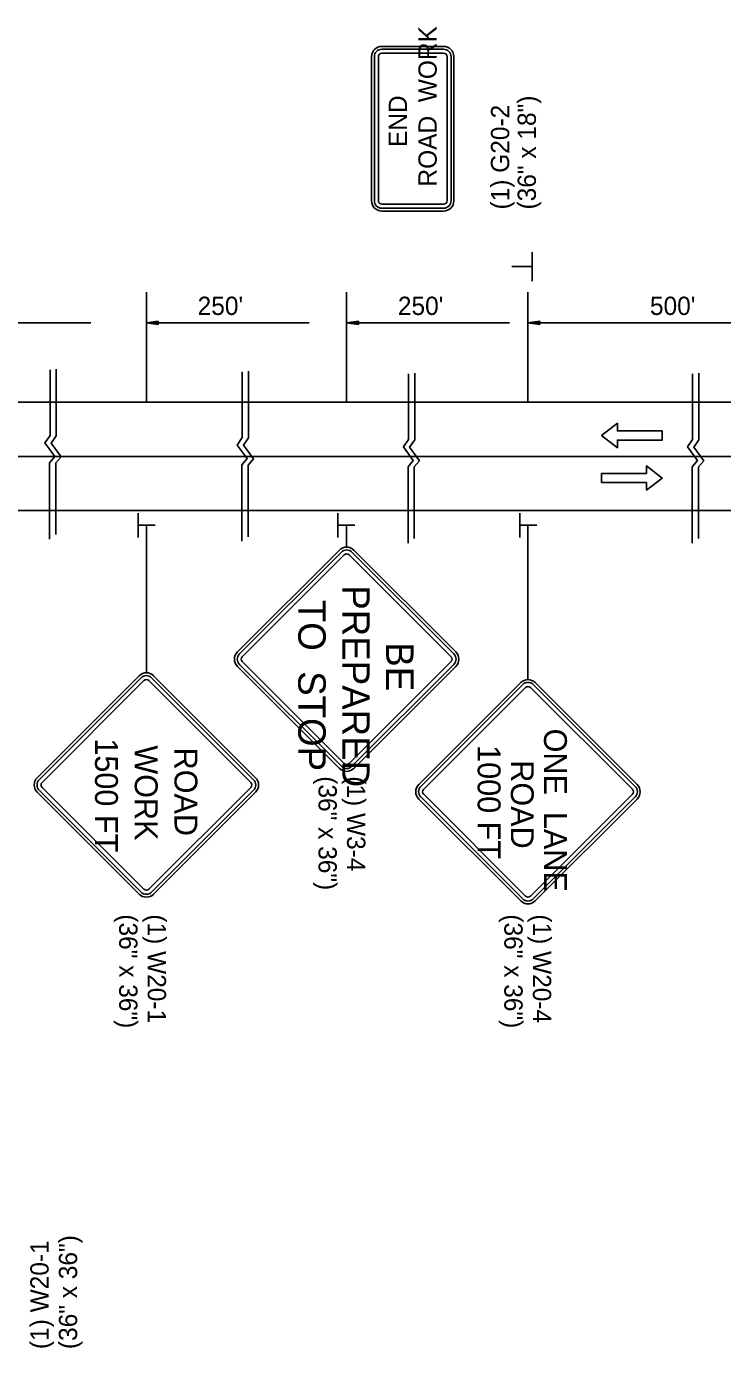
# Model space of a CAD drawing. Extents: x 1927831 to 1930787, y 596452 to 597699.
# Drawn here: x 1928240.2 to 1928468.4, y 597195.5 to 597628.8 of the extents above; entities that cross this region are included whole.
import ezdxf

# ---------------------------------------------------------------- set-up
doc = ezdxf.new("R2010")
doc.units = 0
for name, color, linetype in [('Default', 7, 'Continuous'), ('P_TC_Signs_Permanent', 7, 'Continuous'), ('P_TC_Signs_Temporary', 7, 'Continuous'), ('R_Annotation', 7, 'Continuous'), ('R_Striping', 7, 'Continuous')]:
    doc.layers.add(name, color=color, linetype=linetype)

msp = doc.modelspace()

# ---------------------------------------------------------------- linework, layer by layer
at = {"layer": 'Default'}
for p, q in [((1928406.01, 597554.74), (1928406.01, 597545.26)), ((1928405.87, 597550.02), (1928399.4, 597550.02)), ((1928279.55, 597541.61), (1928279.55, 597505.58)), ((1928345.2, 597541.61), (1928345.2, 597505.58)), ((1928404.65, 597541.61), (1928404.65, 597505.58)), ((1928207.95, 597531.57), (1928261.36, 597531.59)), ((1928283.39, 597532.16), (1928279.55, 597531.59)), ((1928279.55, 597531.59), (1928332.95, 597531.59)), ((1928283.39, 597531.01), (1928279.55, 597531.59)), ((1928283.39, 597532.07), (1928280.19, 597531.59)), ((1928283.39, 597531.11), (1928280.19, 597531.59)), ((1928283.39, 597531.97), (1928280.85, 597531.59)), ((1928283.39, 597531.2), (1928280.85, 597531.59)), ((1928283.39, 597531.87), (1928281.49, 597531.59)), ((1928283.39, 597531.3), (1928281.49, 597531.59)), ((1928283.39, 597531.77), (1928282.14, 597531.59)), ((1928283.39, 597531.4), (1928282.14, 597531.59)), ((1928283.39, 597531.68), (1928282.78, 597531.59)), ((1928283.39, 597531.5), (1928282.78, 597531.59)), ((1928283.39, 597531.01), (1928283.39, 597532.16)), ((1928349.04, 597532.14), (1928345.2, 597531.57)), ((1928345.2, 597531.57), (1928398.6, 597531.57)), ((1928349.04, 597530.99), (1928345.2, 597531.57)), ((1928349.04, 597532.05), (1928345.84, 597531.57)), ((1928349.04, 597531.09), (1928345.84, 597531.57)), ((1928349.04, 597531.95), (1928346.5, 597531.57)), ((1928349.04, 597531.18), (1928346.5, 597531.57)), ((1928349.04, 597531.85), (1928347.14, 597531.57)), ((1928349.04, 597531.28), (1928347.14, 597531.57)), ((1928349.04, 597531.75), (1928347.79, 597531.57)), ((1928349.04, 597531.38), (1928347.79, 597531.57)), ((1928349.04, 597531.66), (1928348.43, 597531.57)), ((1928349.04, 597531.48), (1928348.43, 597531.57)), ((1928349.04, 597530.99), (1928349.04, 597532.14)), ((1928408.49, 597532.14), (1928404.65, 597531.57)), ((1928404.65, 597531.57), (1928504.41, 597531.57)), ((1928408.49, 597530.99), (1928404.65, 597531.57)), ((1928408.49, 597532.05), (1928405.3, 597531.57)), ((1928408.49, 597531.09), (1928405.3, 597531.57)), ((1928408.49, 597531.95), (1928405.96, 597531.57)), ((1928408.49, 597531.18), (1928405.96, 597531.57)), ((1928408.49, 597531.85), (1928406.59, 597531.57)), ((1928408.49, 597531.28), (1928406.59, 597531.57)), ((1928408.49, 597531.75), (1928407.24, 597531.57)), ((1928408.49, 597531.38), (1928407.24, 597531.57)), ((1928408.49, 597531.66), (1928407.89, 597531.57)), ((1928408.49, 597531.48), (1928407.89, 597531.57)), ((1928408.49, 597530.99), (1928408.49, 597532.14)), ((1928044.85, 597505.58), (1929173.7, 597505.58)), ((1927908.3, 597487.79), (1929173.7, 597487.79)), ((1928044.85, 597470), (1929173.7, 597470)), ((1928276.87, 597461.2), (1928276.87, 597469.2)), ((1928342.35, 597461.2), (1928342.35, 597469.2)), ((1928401.98, 597461.2), (1928401.98, 597469.2)), ((1928276.99, 597465.18), (1928282.45, 597465.18)), ((1928342.47, 597465.18), (1928347.93, 597465.18)), ((1928402.1, 597465.18), (1928407.56, 597465.18))]:
    msp.add_line(p, q, dxfattribs=at)
for points in [[(1928247.96, 597516.18), (1928247.96, 597494.66), (1928246.3, 597492.19), (1928249.53, 597487.76), (1928247.83, 597485.71), (1928247.82, 597460.68)], [(1928250, 597516.37), (1928250, 597494.57), (1928248.34, 597492.1), (1928251.58, 597487.67), (1928249.87, 597485.62), (1928249.87, 597462.12)], [(1928311, 597515.51), (1928311, 597493.99), (1928309.34, 597491.51), (1928312.58, 597487.08), (1928310.87, 597485.04), (1928310.87, 597460.01)], [(1928313.04, 597515.7), (1928313.04, 597493.9), (1928311.38, 597491.43), (1928314.62, 597487), (1928312.91, 597484.95), (1928312.91, 597461.45)], [(1928365.46, 597514.86), (1928365.46, 597493.34), (1928363.8, 597490.87), (1928367.04, 597486.44), (1928365.33, 597484.39), (1928365.33, 597459.37)], [(1928367.5, 597515.06), (1928367.5, 597493.25), (1928365.84, 597490.78), (1928369.08, 597486.35), (1928367.38, 597484.31), (1928367.37, 597460.81)], [(1928458.63, 597514.86), (1928458.63, 597493.34), (1928456.96, 597490.87), (1928460.2, 597486.44), (1928458.5, 597484.39), (1928458.49, 597459.37)], [(1928460.67, 597515.06), (1928460.67, 597493.25), (1928459.01, 597490.78), (1928462.25, 597486.35), (1928460.54, 597484.31), (1928460.54, 597460.81)]]:
    msp.add_lwpolyline(points, dxfattribs=at)
at = {"layer": 'P_TC_Signs_Permanent'}
for p, q in [((1928342.81, 597457.08), (1928309.4, 597423.67)), ((1928343.48, 597456.42), (1928310.07, 597423.01)), ((1928344.41, 597455.49), (1928310.99, 597422.08)), ((1928379.41, 597422.08), (1928346, 597455.49)), ((1928380.34, 597423.01), (1928346.92, 597456.42)), ((1928381, 597423.67), (1928347.59, 597457.08)), ((1928309.4, 597418.89), (1928342.81, 597385.48)), ((1928310.07, 597419.56), (1928343.48, 597386.15)), ((1928310.99, 597420.49), (1928344.41, 597387.08)), ((1928346, 597387.08), (1928379.41, 597420.49)), ((1928346.92, 597386.15), (1928380.34, 597419.56)), ((1928347.59, 597385.48), (1928381, 597418.89))]:
    msp.add_line(p, q, dxfattribs=at)
for centre, radius, start, end in [((1928345.2, 597454.69), 3.37, 45, 135), ((1928345.2, 597454.69), 2.44, 45, 135), ((1928345.2, 597454.69), 1.13, 45, 135), ((1928311.79, 597421.28), 3.37, 135, 225), ((1928378.61, 597421.28), 3.37, 315, 45), ((1928311.79, 597421.28), 2.44, 135, 225), ((1928311.79, 597421.28), 1.13, 135, 225), ((1928378.61, 597421.28), 1.13, 315, 45), ((1928378.61, 597421.28), 2.44, 315, 45), ((1928345.2, 597387.87), 3.37, 225, 315), ((1928345.2, 597387.87), 2.44, 225, 315), ((1928345.2, 597387.87), 1.13, 225, 315)]:
    msp.add_arc(centre, radius, start, end, dxfattribs=at)
at = {"layer": 'P_TC_Signs_Temporary'}
for p, q in [((1928353.35, 597618.86), (1928353.35, 597571.61)), ((1928354.29, 597618.86), (1928354.29, 597571.61)), ((1928355.6, 597618.86), (1928355.6, 597571.61)), ((1928376.98, 597622.24), (1928356.73, 597622.24)), ((1928376.98, 597621.3), (1928356.73, 597621.3)), ((1928376.98, 597619.99), (1928356.73, 597619.99)), ((1928378.1, 597571.61), (1928378.1, 597618.86)), ((1928379.41, 597571.61), (1928379.41, 597618.86)), ((1928380.35, 597571.61), (1928380.35, 597618.86)), ((1928356.73, 597570.49), (1928376.98, 597570.49)), ((1928356.73, 597569.17), (1928376.98, 597569.17)), ((1928356.73, 597568.24), (1928376.98, 597568.24)), ((1928243.75, 597382.42), (1928277.16, 597415.83)), ((1928244.41, 597381.76), (1928277.82, 597415.17)), ((1928281.27, 597415.17), (1928314.68, 597381.76)), ((1928281.93, 597415.83), (1928315.35, 597382.42)), ((1928245.34, 597380.83), (1928278.75, 597414.24)), ((1928280.34, 597414.24), (1928313.75, 597380.83)), ((1928368.86, 597380.2), (1928402.27, 597413.61)), ((1928369.52, 597379.54), (1928402.93, 597412.95)), ((1928370.45, 597378.61), (1928403.86, 597412.02)), ((1928405.45, 597412.02), (1928438.86, 597378.61)), ((1928406.38, 597412.95), (1928439.79, 597379.54)), ((1928407.04, 597413.61), (1928440.45, 597380.2)), ((1928277.16, 597344.24), (1928243.75, 597377.65)), ((1928277.82, 597344.9), (1928244.41, 597378.31)), ((1928278.75, 597345.83), (1928245.34, 597379.24)), ((1928313.75, 597379.24), (1928280.34, 597345.83)), ((1928314.68, 597378.31), (1928281.27, 597344.9)), ((1928315.35, 597377.65), (1928281.93, 597344.24)), ((1928402.27, 597342.02), (1928368.86, 597375.43)), ((1928402.93, 597342.68), (1928369.52, 597376.09)), ((1928403.86, 597343.61), (1928370.45, 597377.02)), ((1928438.86, 597377.02), (1928405.45, 597343.61)), ((1928439.79, 597376.09), (1928406.38, 597342.68)), ((1928440.45, 597375.43), (1928407.04, 597342.02))]:
    msp.add_line(p, q, dxfattribs=at)
for centre, radius, start, end in [((1928356.73, 597618.86), 3.37, 90, 180), ((1928356.73, 597618.86), 2.44, 90, 180), ((1928356.73, 597618.86), 1.13, 90, 180), ((1928376.98, 597618.86), 3.37, 360, 90), ((1928376.98, 597618.86), 2.44, 360, 90), ((1928376.98, 597618.86), 1.13, 360, 90), ((1928356.73, 597571.61), 3.37, 180, 270), ((1928356.73, 597571.61), 2.44, 180, 270), ((1928356.73, 597571.61), 1.13, 180, 270), ((1928376.98, 597571.61), 2.44, 270, 360), ((1928376.98, 597571.61), 1.13, 270, 360), ((1928376.98, 597571.61), 3.37, 270, 360), ((1928279.55, 597413.45), 3.37, 45, 135), ((1928279.55, 597413.45), 2.44, 45, 135), ((1928279.55, 597413.45), 1.12, 45, 135), ((1928404.65, 597411.22), 3.37, 45, 135), ((1928404.65, 597411.22), 2.44, 45, 135), ((1928404.65, 597411.22), 1.12, 45, 135), ((1928246.14, 597380.04), 3.37, 135, 225), ((1928246.14, 597380.04), 2.44, 135, 225), ((1928246.14, 597380.04), 1.13, 135, 225), ((1928312.96, 597380.04), 1.13, 315, 45), ((1928312.96, 597380.04), 2.44, 315, 45), ((1928312.96, 597380.04), 3.37, 315, 45), ((1928371.24, 597377.81), 3.37, 135, 225), ((1928438.06, 597377.81), 3.37, 315, 45), ((1928371.24, 597377.81), 2.44, 135, 225), ((1928371.24, 597377.81), 1.13, 135, 225), ((1928438.06, 597377.81), 1.13, 315, 45), ((1928438.06, 597377.81), 2.44, 315, 45), ((1928279.55, 597346.63), 1.12, 225, 315), ((1928279.55, 597346.63), 3.37, 225, 315), ((1928279.55, 597346.63), 2.44, 225, 315), ((1928404.65, 597344.4), 3.37, 225, 315), ((1928404.65, 597344.4), 2.44, 225, 315), ((1928404.65, 597344.4), 1.12, 225, 315)]:
    msp.add_arc(centre, radius, start, end, dxfattribs=at)
at = {"layer": 'R_Annotation'}
for p, q in [((1928279.55, 597465.18), (1928279.55, 597416.82)), ((1928345.2, 597465.18), (1928345.2, 597458.07)), ((1928404.65, 597465.18), (1928404.65, 597414.6))]:
    msp.add_line(p, q, dxfattribs=at)
at = {"layer": 'R_Striping'}
for points in [[(1928433.95, 597498.63), (1928428.75, 597494.63), (1928433.95, 597490.63), (1928433.95, 597493.13), (1928448.66, 597493.13), (1928448.66, 597496.13), (1928433.95, 597496.13)], [(1928443.47, 597476.68), (1928448.66, 597480.68), (1928443.47, 597484.68), (1928443.47, 597482.18), (1928428.75, 597482.18), (1928428.75, 597479.18), (1928443.47, 597479.18)]]:
    msp.add_lwpolyline(points, close=True, dxfattribs=at)

# ---------------------------------------------------------------- texts
at = {"layer": 'Default'}
for s, p in [("250'", (1928296.35, 597534.16)), ("250'", (1928362, 597534.16)), ("500'", (1928444.63, 597534.16))]:
    msp.add_text(s, height=6, rotation=360, dxfattribs=at).set_placement(p)
at = {"layer": 'P_TC_Signs_Temporary'}
for s, height, rotation, p in [('ROAD  WORK', 6, 90, (1928374.73, 597576.28)), ('END', 6, 90, (1928364.98, 597589.21)), ('TO  STOP', 9, 270, (1928329.33, 597440.75)), ('PREPARED', 9, 270, (1928343.73, 597445.52)), ('BE', 9, 270, (1928358.13, 597426.83)), ('ONE  LANE', 7.5, 270, (1928409.9, 597398.51)), ('1500 FT', 7.5, 270, (1928262.71, 597395.33)), ('WORK', 7.5, 270, (1928275.74, 597393.03)), (' ROAD ', 7.5, 270, (1928288.76, 597395.06)), ('1000 FT', 7.5, 270, (1928388.15, 597393.1)), ('ROAD', 7.5, 270, (1928399.03, 597388.12))]:
    msp.add_text(s, height=height, rotation=rotation, dxfattribs=at).set_placement(p)
at = {"layer": 'R_Annotation'}
for s, height, rotation, p in [('(36" x 18")', 5.9996, 90, (1928407.25, 597568.75)), ('(1) G20-2', 6, 90, (1928398.5, 597568.75)), ('(36" x 36")', 5.9996, 270, (1928335.97, 597382.88)), ('(1) W3-4', 6, 270, (1928345.33, 597382.88)), ('(36" x 36")', 5.9996, 270, (1928270.63, 597337.6)), ('(1) W20-1', 6, 270, (1928279.99, 597337.6)), ('(36" x 36")', 5.9996, 270, (1928396.89, 597337.6)), ('(1) W20-4', 6, 270, (1928406.25, 597337.6)), ('(1) W20-1', 6, 90, (1928247.49, 597195.04)), ('(36" x 36")', 5.9996, 90, (1928256.85, 597195.04))]:
    msp.add_text(s, height=height, rotation=rotation, dxfattribs=at).set_placement(p)

doc.saveas('drawing.dxf')
